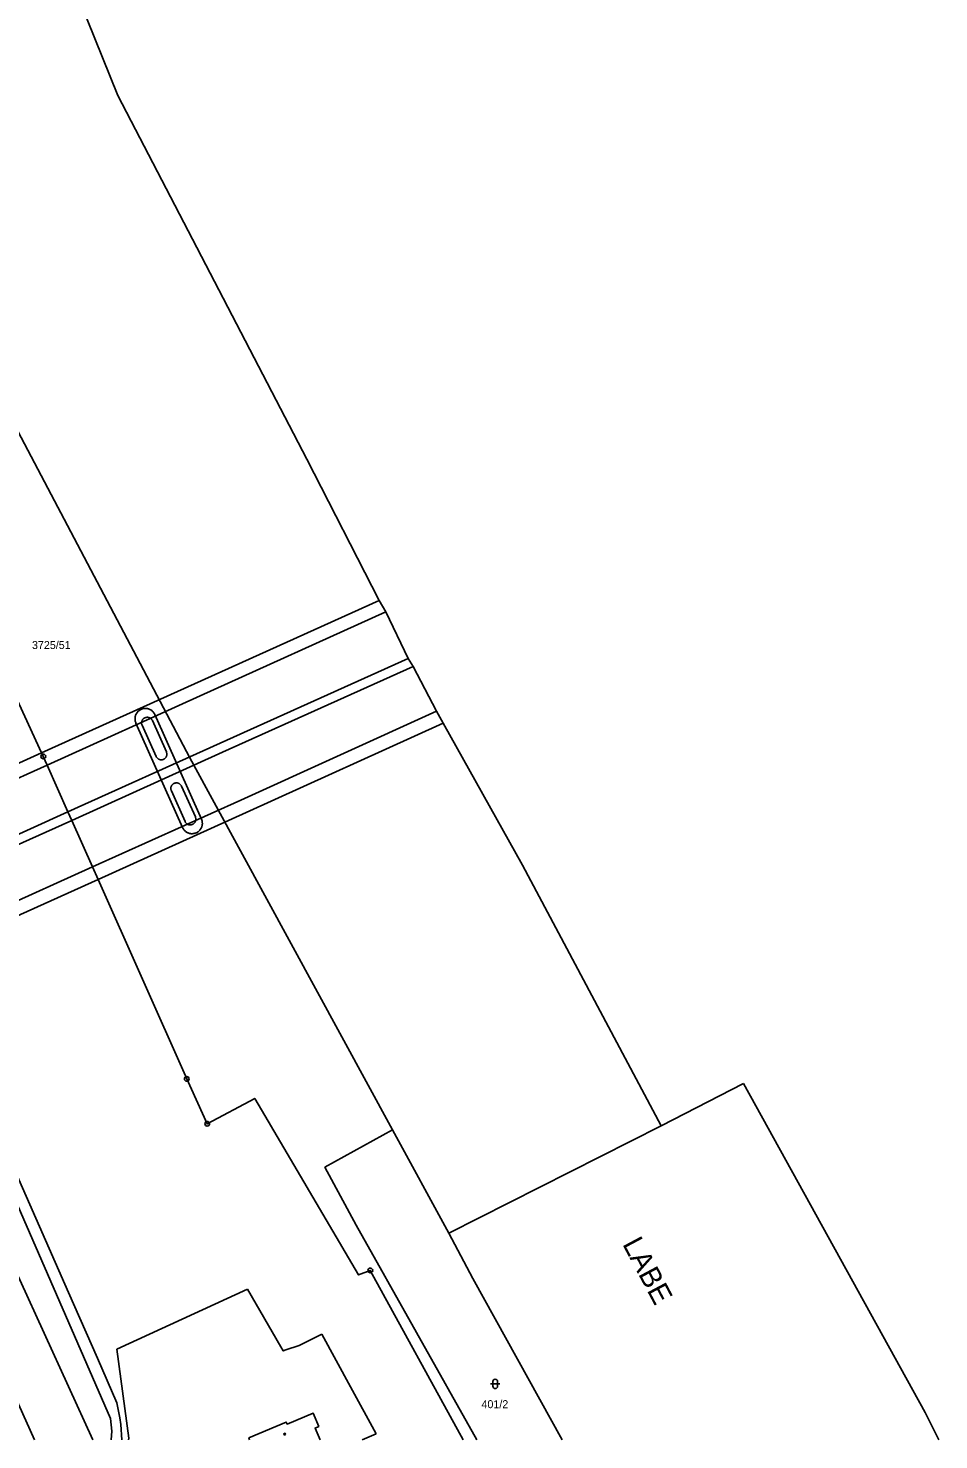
# Model space of a CAD drawing. Extents: x -747779 to -747197, y -965543 to -964919.
# Drawn here: x -747390.8 to -747197.2, y -965537.7 to -965237.8 of the extents above; entities that cross this region are included whole.
import ezdxf

# ---------------------------------------------------------------- set-up
doc = ezdxf.new("R2010")
doc.units = 0
for name, color, linetype in [('Hranice parcel', 7, 'Continuous'), ('Parcelní čísla', 7, 'Continuous'), ('Pop  PČ popisy', 7, 'Continuous'), ('Vnitřní kresba', 7, 'Continuous'), ('Značky bodu BP', 7, 'Continuous'), ('Značky budov', 7, 'Continuous'), ('Značky kultur', 7, 'Continuous')]:
    doc.layers.add(name, color=color, linetype=linetype)

msp = doc.modelspace()

# ---------------------------------------------------------------- linework, layer by layer
at = {"layer": 'Hranice parcel'}
for p, q in [((-747238.75, -965462.02), (-747256.24, -965470.98)), ((-747200.15, -965531.89), (-747238.75, -965462.02)), ((-747313.39, -965471.85), (-747301.42, -965493.8)), ((-747301.42, -965493.8), (-747256.24, -965470.98)), ((-747197.22, -965537.69), (-747200.15, -965531.89))]:
    msp.add_line(p, q, dxfattribs=at)
for points in [[(-747316.19, -965359.38), (-747331.6, -965329.38), (-747371.79, -965252.1), (-747392.97, -965199.55), (-747407.19, -965162.14)], [(-747298.39, -965537.69), (-747318.1, -965501.72), (-747320.58, -965502.66), (-747342.67, -965465.16), (-747352.78, -965470.55), (-747357.13, -965461.03), (-747376, -965418.63), (-747377.18, -965415.98), (-747381.59, -965406.09), (-747382.39, -965404.29), (-747386.82, -965394.33), (-747387.63, -965392.51), (-747387.99, -965391.72), (-747426.3, -965308.51), (-747438.98, -965282.25)], [(-747397.43, -965314.99), (-747396.55, -965316.79), (-747356.48, -965392.83), (-747313.39, -965471.85)], [(-747302.6, -965385.45), (-747304.02, -965382.92), (-747309, -965373.41), (-747310.05, -965371.67), (-747314.8, -965361.81), (-747316.19, -965359.38)], [(-747256.24, -965470.98), (-747285.74, -965415.6), (-747302.6, -965385.45)], [(-747370.93, -965537.69), (-747371.14, -965534.42), (-747371.37, -965533), (-747372.01, -965529.87), (-747376.13, -965520.36), (-747382.27, -965506.43), (-747407.33, -965449.67), (-747407.84, -965446.87), (-747406.56, -965444.53), (-747404.36, -965442.75), (-747405.91, -965440.89), (-747407.09, -965439.7), (-747408.25, -965437.2), (-747409.14, -965440.59), (-747412.27, -965439.07), (-747413.8, -965435.67)], [(-747377.11, -965537.69), (-747403.05, -965481.03), (-747419.59, -965443.86), (-747421.02, -965440.66)], [(-747423.22, -965466.19), (-747419.51, -965470.69), (-747413.64, -965484.08), (-747404.72, -965503.92), (-747389.51, -965537.69)], [(-747313.39, -965471.85), (-747327.76, -965479.79), (-747321.1, -965492.1), (-747295.48, -965537.69)], [(-747301.42, -965493.8), (-747296.32, -965503.4), (-747277.3, -965537.69)], [(-747343.76, -965537.69), (-747343.93, -965537.29), (-747335.96, -965533.93), (-747335.79, -965534.35), (-747330.26, -965532.02), (-747329.05, -965534.87), (-747329.84, -965535.2), (-747328.79, -965537.69)]]:
    msp.add_lwpolyline(points, dxfattribs=at)
at = {"layer": 'Vnitřní kresba'}
for p, q in [((-747355.47, -965377.05), (-747316.19, -965359.38)), ((-747354.3, -965379.65), (-747314.8, -965361.81)), ((-747350.06, -965389.71), (-747310.05, -965371.67)), ((-747349.5, -965391.61), (-747309, -965373.41)), ((-747355.47, -965377.05), (-747387.99, -965391.72)), ((-747386.82, -965394.33), (-747354.3, -965379.65)), ((-747345.66, -965401.77), (-747304.02, -965382.92)), ((-747367.94, -965385.41), (-747358.02, -965407.62)), ((-747366.63, -965385.89), (-747363.66, -965392.52)), ((-747364.44, -965384.9), (-747361.47, -965391.54)), ((-747363.92, -965383.61), (-747354, -965405.83)), ((-747344.47, -965404.41), (-747302.6, -965385.45)), ((-747387.99, -965391.72), (-747421.99, -965407.05)), ((-747350.06, -965389.71), (-747382.39, -965404.29)), ((-747349.5, -965391.61), (-747381.59, -965406.09)), ((-747420.79, -965409.68), (-747386.82, -965394.33)), ((-747360.41, -965399.82), (-747357.49, -965406.35)), ((-747358.22, -965398.84), (-747355.3, -965405.37)), ((-747377.18, -965415.98), (-747345.66, -965401.77)), ((-747382.39, -965404.29), (-747416.28, -965419.57)), ((-747381.59, -965406.09), (-747415.46, -965421.36)), ((-747344.47, -965404.41), (-747376, -965418.63)), ((-747410.96, -965431.22), (-747377.18, -965415.98)), ((-747376, -965418.63), (-747409.76, -965433.85)), ((-747373.33, -965533.21), (-747414.31, -965439.35)), ((-747371.97, -965518.45), (-747344.25, -965505.68)), ((-747333.24, -965517.67), (-747336.05, -965518.62)), ((-747333.24, -965517.67), (-747328.42, -965515.29)), ((-747328.42, -965515.29), (-747322.34, -965526.42)), ((-747369.47, -965537.32), (-747371.97, -965518.45)), ((-747322.34, -965526.42), (-747316.85, -965536.46)), ((-747373.06, -965535.89), (-747373.33, -965533.21)), ((-747373.23, -965537.69), (-747373.06, -965535.89)), ((-747369.53, -965537.69), (-747369.47, -965537.32)), ((-747316.85, -965536.46), (-747319.8, -965537.69))]:
    msp.add_line(p, q, dxfattribs=at)
for points in [[(-747363.92, -965383.61), (-747363.98, -965383.49), (-747364.04, -965383.38), (-747364.11, -965383.27), (-747364.19, -965383.16), (-747364.27, -965383.06), (-747364.36, -965382.97), (-747364.45, -965382.88), (-747364.55, -965382.79), (-747364.66, -965382.71), (-747364.77, -965382.64), (-747364.88, -965382.58), (-747364.99, -965382.52), (-747365.11, -965382.46), (-747365.24, -965382.42), (-747365.36, -965382.38), (-747365.49, -965382.35), (-747365.62, -965382.33), (-747365.75, -965382.32), (-747365.88, -965382.31), (-747366.01, -965382.31), (-747366.14, -965382.32), (-747366.27, -965382.33), (-747366.4, -965382.36), (-747366.52, -965382.39), (-747366.65, -965382.43), (-747366.77, -965382.47), (-747366.89, -965382.53), (-747367.01, -965382.59), (-747367.12, -965382.66), (-747367.22, -965382.73), (-747367.33, -965382.81), (-747367.43, -965382.89), (-747367.52, -965382.99), (-747367.61, -965383.08), (-747367.69, -965383.18), (-747367.76, -965383.29), (-747367.83, -965383.4), (-747367.9, -965383.52), (-747367.95, -965383.63), (-747368, -965383.76), (-747368.04, -965383.88), (-747368.07, -965384.01), (-747368.1, -965384.13), (-747368.12, -965384.26), (-747368.13, -965384.39), (-747368.13, -965384.52), (-747368.13, -965384.65), (-747368.11, -965384.78), (-747368.09, -965384.91), (-747368.07, -965385.04), (-747368.03, -965385.17), (-747367.99, -965385.29), (-747367.94, -965385.41)], [(-747364.44, -965384.9), (-747364.48, -965384.81), (-747364.53, -965384.73), (-747364.59, -965384.65), (-747364.65, -965384.58), (-747364.72, -965384.51), (-747364.8, -965384.45), (-747364.87, -965384.39), (-747364.96, -965384.34), (-747365.04, -965384.3), (-747365.13, -965384.26), (-747365.23, -965384.23), (-747365.32, -965384.21), (-747365.42, -965384.2), (-747365.51, -965384.19), (-747365.61, -965384.2), (-747365.71, -965384.21), (-747365.8, -965384.22), (-747365.89, -965384.25), (-747365.99, -965384.28), (-747366.07, -965384.32), (-747366.16, -965384.37), (-747366.24, -965384.42), (-747366.32, -965384.48), (-747366.39, -965384.55), (-747366.45, -965384.62), (-747366.51, -965384.69), (-747366.56, -965384.78), (-747366.61, -965384.86), (-747366.65, -965384.95), (-747366.68, -965385.04), (-747366.71, -965385.13), (-747366.72, -965385.23), (-747366.73, -965385.32), (-747366.74, -965385.42), (-747366.73, -965385.52), (-747366.72, -965385.61), (-747366.7, -965385.71), (-747366.67, -965385.8), (-747366.63, -965385.89)], [(-747361.47, -965391.54), (-747361.44, -965391.63), (-747361.41, -965391.72), (-747361.39, -965391.82), (-747361.37, -965391.91), (-747361.37, -965392.01), (-747361.37, -965392.1), (-747361.38, -965392.2), (-747361.4, -965392.29), (-747361.42, -965392.39), (-747361.46, -965392.48), (-747361.5, -965392.57), (-747361.54, -965392.65), (-747361.6, -965392.73), (-747361.66, -965392.81), (-747361.72, -965392.88), (-747361.79, -965392.94), (-747361.87, -965393), (-747361.95, -965393.05), (-747362.03, -965393.1), (-747362.12, -965393.14), (-747362.21, -965393.17), (-747362.31, -965393.2), (-747362.4, -965393.21), (-747362.5, -965393.22), (-747362.59, -965393.22), (-747362.69, -965393.22), (-747362.78, -965393.2), (-747362.88, -965393.18), (-747362.97, -965393.15), (-747363.06, -965393.12), (-747363.15, -965393.08), (-747363.23, -965393.03), (-747363.31, -965392.97), (-747363.38, -965392.91), (-747363.45, -965392.84), (-747363.51, -965392.77), (-747363.57, -965392.69), (-747363.62, -965392.61), (-747363.66, -965392.52)], [(-747360.41, -965399.82), (-747360.45, -965399.73), (-747360.47, -965399.64), (-747360.5, -965399.54), (-747360.51, -965399.45), (-747360.52, -965399.35), (-747360.51, -965399.25), (-747360.5, -965399.16), (-747360.49, -965399.06), (-747360.46, -965398.97), (-747360.43, -965398.88), (-747360.39, -965398.79), (-747360.34, -965398.71), (-747360.29, -965398.62), (-747360.23, -965398.55), (-747360.16, -965398.48), (-747360.09, -965398.41), (-747360.02, -965398.35), (-747359.94, -965398.3), (-747359.85, -965398.25), (-747359.76, -965398.21), (-747359.67, -965398.18), (-747359.58, -965398.16), (-747359.48, -965398.14), (-747359.39, -965398.13), (-747359.29, -965398.13), (-747359.19, -965398.13), (-747359.1, -965398.15), (-747359, -965398.17), (-747358.91, -965398.2), (-747358.82, -965398.23), (-747358.73, -965398.28), (-747358.65, -965398.33), (-747358.57, -965398.39), (-747358.5, -965398.45), (-747358.43, -965398.52), (-747358.37, -965398.59), (-747358.31, -965398.67), (-747358.26, -965398.75), (-747358.22, -965398.84)], [(-747354, -965405.83), (-747353.95, -965405.95), (-747353.91, -965406.07), (-747353.87, -965406.2), (-747353.85, -965406.33), (-747353.83, -965406.46), (-747353.82, -965406.59), (-747353.81, -965406.72), (-747353.81, -965406.85), (-747353.83, -965406.98), (-747353.84, -965407.1), (-747353.87, -965407.23), (-747353.91, -965407.36), (-747353.95, -965407.48), (-747353.99, -965407.6), (-747354.05, -965407.72), (-747354.11, -965407.83), (-747354.18, -965407.95), (-747354.26, -965408.05), (-747354.34, -965408.15), (-747354.43, -965408.25), (-747354.52, -965408.34), (-747354.62, -965408.43), (-747354.72, -965408.51), (-747354.83, -965408.58), (-747354.94, -965408.65), (-747355.06, -965408.71), (-747355.18, -965408.76), (-747355.3, -965408.8), (-747355.42, -965408.84), (-747355.55, -965408.87), (-747355.68, -965408.9), (-747355.81, -965408.91), (-747355.94, -965408.92), (-747356.07, -965408.92), (-747356.2, -965408.92), (-747356.33, -965408.9), (-747356.45, -965408.88), (-747356.58, -965408.85), (-747356.71, -965408.81), (-747356.83, -965408.77), (-747356.95, -965408.71), (-747357.06, -965408.65), (-747357.18, -965408.59), (-747357.29, -965408.52), (-747357.39, -965408.44), (-747357.49, -965408.35), (-747357.58, -965408.26), (-747357.67, -965408.17), (-747357.75, -965408.07), (-747357.83, -965407.96), (-747357.9, -965407.85), (-747357.96, -965407.74), (-747358.02, -965407.62)], [(-747357.49, -965406.35), (-747357.45, -965406.44), (-747357.4, -965406.52), (-747357.34, -965406.6), (-747357.28, -965406.67), (-747357.21, -965406.74), (-747357.14, -965406.8), (-747357.06, -965406.86), (-747356.98, -965406.91), (-747356.89, -965406.95), (-747356.8, -965406.99), (-747356.71, -965407.02), (-747356.61, -965407.04), (-747356.52, -965407.05), (-747356.42, -965407.06), (-747356.33, -965407.06), (-747356.23, -965407.05), (-747356.14, -965407.03), (-747356.04, -965407), (-747355.95, -965406.97), (-747355.86, -965406.93), (-747355.78, -965406.89), (-747355.7, -965406.83), (-747355.62, -965406.77), (-747355.55, -965406.71), (-747355.48, -965406.64), (-747355.43, -965406.56), (-747355.37, -965406.48), (-747355.32, -965406.4), (-747355.29, -965406.31), (-747355.25, -965406.22), (-747355.23, -965406.12), (-747355.21, -965406.03), (-747355.2, -965405.93), (-747355.2, -965405.84), (-747355.2, -965405.74), (-747355.21, -965405.65), (-747355.24, -965405.55), (-747355.26, -965405.46), (-747355.3, -965405.37)], [(-747344.25, -965505.68), (-747337.12, -965517.93), (-747336.61, -965518.81), (-747336.05, -965518.62)]]:
    msp.add_lwpolyline(points, dxfattribs=at)
at = {"layer": 'Značky bodu BP'}
for centre, radius in [((-747387.63, -965392.51), 0.5), ((-747387.63, -965392.51), 0.0303), ((-747357.13, -965461.03), 0.5), ((-747357.13, -965461.03), 0.0303), ((-747352.78, -965470.55), 0.5), ((-747352.78, -965470.55), 0.0303), ((-747318.1, -965501.72), 0.5), ((-747318.1, -965501.72), 0.0303)]:
    msp.add_circle(centre, radius, dxfattribs=at)
at = {"layer": 'Značky budov'}
msp.add_circle((-747336.33, -965536.5), 0.175, dxfattribs=at)
at = {"layer": 'Značky kultur'}
for p, q in [((-747292.55, -965525.83), (-747290.55, -965525.83)), ((-747292.05, -965525.33), (-747292.05, -965526.33)), ((-747291.05, -965526.33), (-747291.05, -965525.33))]:
    msp.add_line(p, q, dxfattribs=at)
for centre, start, end in [((-747291.55, -965525.33), 0, 180), ((-747291.55, -965526.33), 180, 359.9879)]:
    msp.add_arc(centre, 0.5, start, end, dxfattribs=at)

# ---------------------------------------------------------------- texts
at = {"layer": 'Parcelní čísla'}
for s, p in [('3725/51', (-747390.04, -965369.69)), ('401/2', (-747294.46, -965530.98))]:
    msp.add_text(s, height=1.7, dxfattribs=at).set_placement(p)
at = {"layer": 'Pop  PČ popisy'}
msp.add_text('LABE', height=4.4, rotation=298, dxfattribs=at).set_placement((-747264.58, -965496.1))

doc.saveas('drawing.dxf')
